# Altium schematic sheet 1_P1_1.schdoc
size 309 x 223 mm; Symbol: Sheet-Symbol_A4; Device: Sheet-Symbol_A4; @Page Name: P1_1; @Page Count: 1; @Page No: 1; @Project Name: 8266; @Schematic Name: Schematic1; @Update Date: 2023-04-14; Company: 嘉立创EDA; Page Size: 4K; Version: V1.0
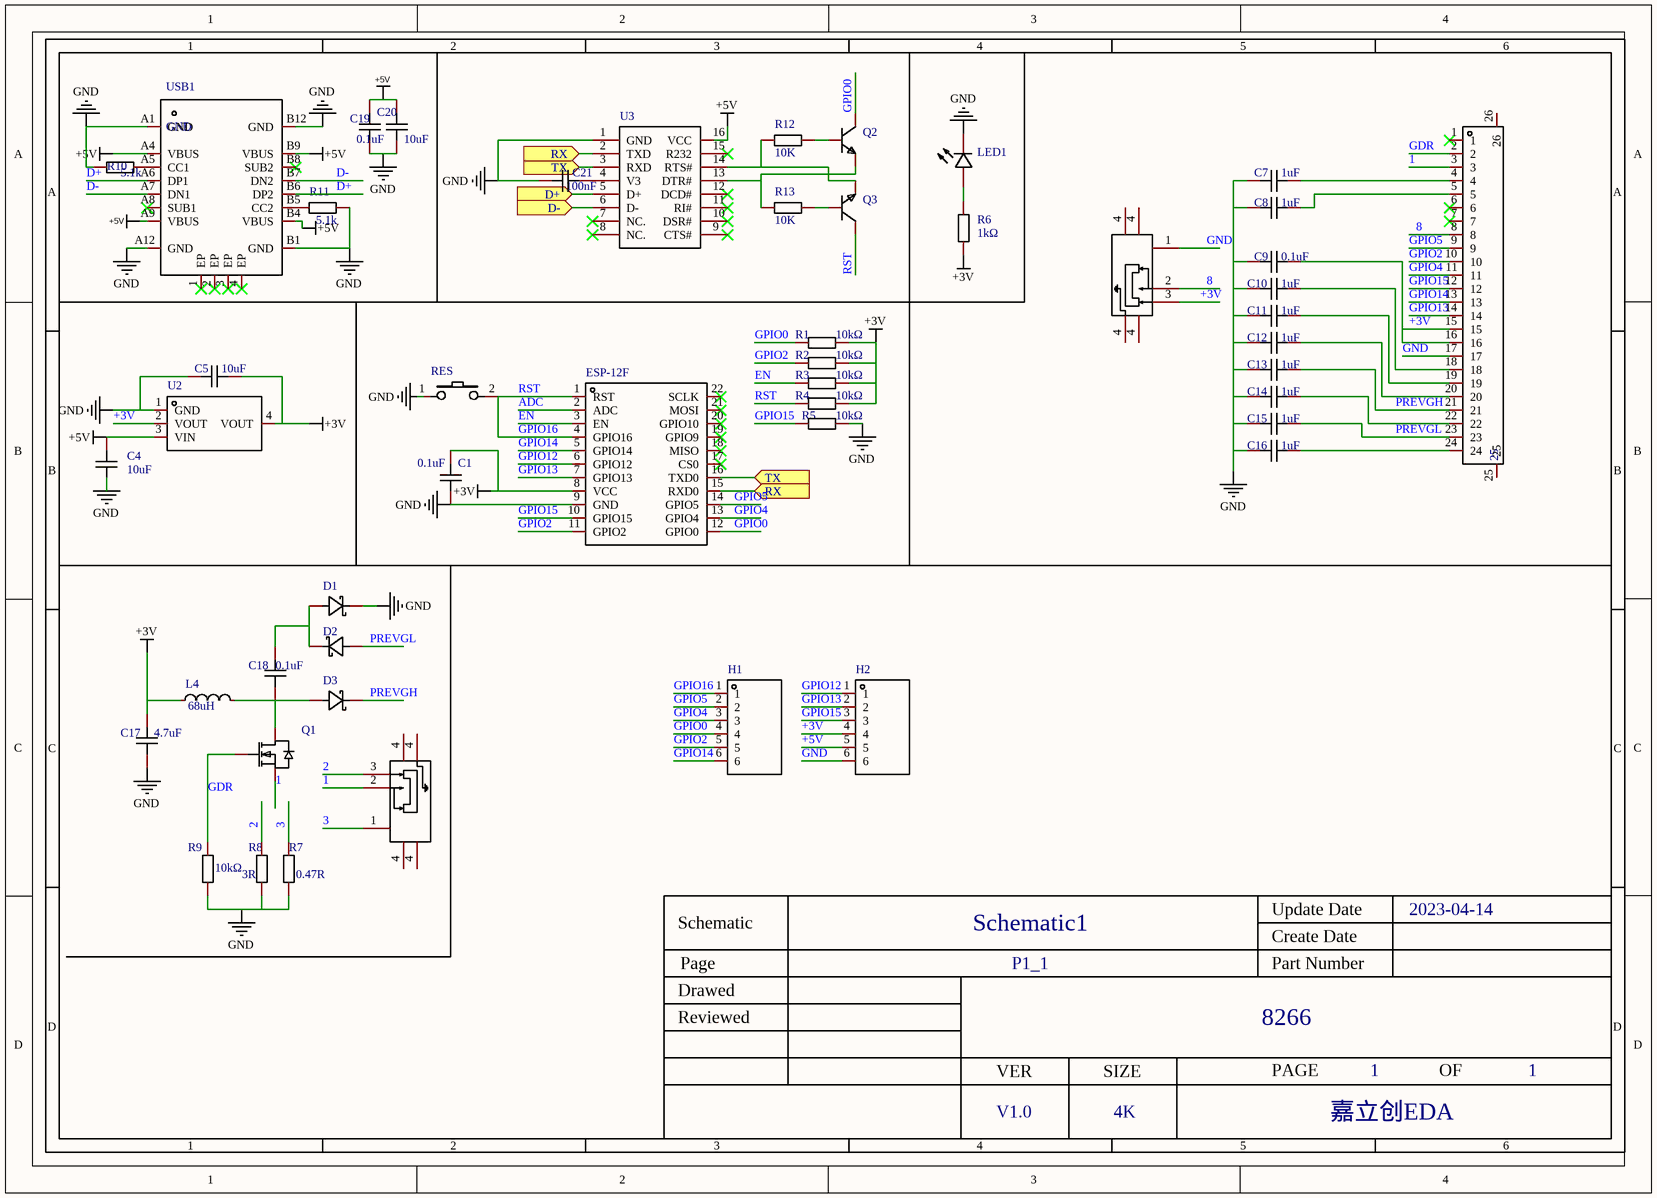
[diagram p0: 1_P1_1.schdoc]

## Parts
C1  value 0.1uF  [C0402]  (hidden comment: CC0603KRX7R9BB104)
C4  value 10uF  [C0402]  (hidden comment: CC0603KRX7R9BB104)
C5  value 10uF  [C0402]  (hidden comment: CC0603KRX7R9BB104)
C7  value 1uF  [C0402]  (hidden comment: CC0603KRX7R9BB104)
C8  value 1uF  [C0402]  (hidden comment: CC0603KRX7R9BB104)
C9  value 0.1uF  [C0402]  (hidden comment: CC0603KRX7R9BB104)
C10  value 1uF  [C0402]  (hidden comment: CC0603KRX7R9BB104)
C11  value 1uF  [C0402]  (hidden comment: CC0603KRX7R9BB104)
C12  value 1uF  [C0402]  (hidden comment: CC0603KRX7R9BB104)
C13  value 1uF  [C0402]  (hidden comment: CC0603KRX7R9BB104)
C14  value 1uF  [C0402]  (hidden comment: CC0603KRX7R9BB104)
C15  value 1uF  [C0402]  (hidden comment: CC0603KRX7R9BB104)
C16  value 1uF  [C0402]  (hidden comment: CC0603KRX7R9BB104)
C17  value 4.7uF  [C0402]  (hidden comment: CC0603KRX7R9BB104)
C18  value 0.1uF  [C0402]  (hidden comment: CC0603KRX7R9BB104)
C19  value 0.1uF  [C0402]  (hidden comment: CC0603KRX7R9BB104)
C20  value 10uF  [C0402]  (hidden comment: CC0603KRX7R9BB104)
C21  value 100nF  [C0603]  (hidden comment: CAP_0603)
D1  MBR0530_C699108  [SOD-123_L2.7-W1.6-LS3.7-RD-1]  (value not drawn)
D2  MBR0530_C699108  [SOD-123_L2.7-W1.6-LS3.7-RD-1]  (value not drawn)
D3  MBR0530_C699108  [SOD-123_L2.7-W1.6-LS3.7-RD-1]  (value not drawn)
ESP-12F  ESP-12F(ESP8266MOD)  [WIFIM-SMD_ESP-12F-ESP8266MOD]  (value not drawn)
FPC1  NAME: 25  [FPC-SMD_24P-P0.50_HDGC_0.5K-BS-24PWB]  (hidden comment: 0.5K-BS-24PWB)
H1  Z-211-0611-0021-001  [HDR-TH_6P-P2.54-V_Z-211-0611-0021-001]  (value not drawn)
H2  Z-211-0611-0021-001  [HDR-TH_6P-P2.54-V_Z-211-0611-0021-001]  (value not drawn)
L4  value 68uH  [IND-SMD_L4.0-W4.0_SWPA4018S]  (hidden comment: SWPA4018S680MT)
LED1  19-217/R6C-AL1M2VY/3T  [LED0603-R-RD]  (value not drawn)
Q1  AO3400  [SOT-23-3_L3.0-W1.7-P0.95-LS2.9-BR]  (value not drawn)
Q2  S8050_NPN  [SOT-23_L2.9-W1.3-P1.90-LS2.4-BR]  (value not drawn)
Q3  S8050_NPN  [SOT-23_L2.9-W1.3-P1.90-LS2.4-BR]  (value not drawn)
R1  value 10kΩ  [R0603]  (hidden comment: TR0603B10K0P0525Z)
R2  value 10kΩ  [R0603]  (hidden comment: TR0603B10K0P0525Z)
R3  value 10kΩ  [R0603]  (hidden comment: TR0603B10K0P0525Z)
R4  value 10kΩ  [R0603]  (hidden comment: TR0603B10K0P0525Z)
R5  value 10kΩ  [R0603]  (hidden comment: TR0603B10K0P0525Z)
R6  value 1kΩ  [R0603]  (hidden comment: TR0603B10K0P0525Z)
R7  value 0.47R  [R0603]  (hidden comment: TR0603B10K0P0525Z)
R8  value 3R  [R0603]  (hidden comment: TR0603B10K0P0525Z)
R9  value 10kΩ  [R0603]  (hidden comment: TR0603B10K0P0525Z)
R10  value 5.1k  [R0603]  (hidden comment: Res_0603)
R11  value 5.1k  [R0603]  (hidden comment: Res_0603)
R12  value 10K  [R0603]  (hidden comment: Res_0603)
R13  value 10K  [R0603]  (hidden comment: Res_0603)
RES  TC-3602-4.3-260G  [KEY-SMD_L6.0-W3.6-LS8.3-L]  (value not drawn)
SW1  MSK12C02  [SW-TH_MSK12C02]  (value not drawn)
SW2  MSK12C02  [SW-TH_MSK12C02]  (value not drawn)
U2  AMS1117-2.5_C498436  [SOT-223-3_L6.7-W3.7-P2.30-LS7.0-BR]  (value not drawn)
U3  CH340C  [SOP-16_L10.0-W3.9-P1.27-LS6.0-BL]  (value not drawn)
USB1  NAME: GND  [USB-C-SMD_KH-TYPE-C-16P]  (hidden comment: USB_TYPE-C-16P)

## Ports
D+ (in), D- (in), RX (in), TX (in)

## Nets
+3V: C1.2 C5.1 C9.2 C17.2 ESP-12F.8(VCC) FPC1.15 FPC1.16 H2.4 L4.1 R1.2 R2.2 R3.2 R4.2 R6.1 SW1.3 U2.2(VOUT) U2.4(VOUT)
+5V: C4.2 C19.2 C20.2 H2.5 U2.3(VIN) U3.16(VCC) USB1.A4(VBUS) USB1.A9(VBUS) USB1.B4(VBUS) USB1.B9(VBUS)
GND: C1.1 C4.1 C5.2 C7.1 C8.1 C9.1 C10.1 C11.1 C12.1 C13.1 C14.1 C15.1 C16.1 C17.1 C19.1 C20.1 C21.1 D1.1(K) ESP-12F.9(GND) FPC1.17 H2.6 LED1.2(C) R5.2 R7.1 R8.1 R9.1 R10.1 R11.2 RES.1 SW1.1 U2.1(GND) U3.1(GND) USB1.A1(GND) USB1.A12(GND) USB1.B1(GND) USB1.B12(GND)
1: FPC1.3 Q1.2(S) SW2.2
2: R8.2 SW2.3
3: R7.2 SW2.1
8: FPC1.8 SW1.2
ADC: ESP-12F.2(ADC)
D+: USB1.A6(DP1) USB1.B6(DP2)
D+: U3.5(D+) ; port D+  [a separate net that carries the same name]
D-: USB1.A7(DN1) USB1.B7(DN2)
D-: U3.6(D-) ; port D-  [a separate net that carries the same name]
EN: ESP-12F.3(EN) R3.1
GDR: FPC1.2 Q1.1(G) R9.2
GPIO0: ESP-12F.12(GPIO0) H1.4 Q2.3(C) R1.1
GPIO2: ESP-12F.11(GPIO2) FPC1.10 H1.5 R2.1
GPIO4: ESP-12F.13(GPIO4) FPC1.11 H1.3
GPIO5: ESP-12F.14(GPIO5) FPC1.9 H1.2
GPIO12: ESP-12F.6(GPIO12) H2.1
GPIO13: ESP-12F.7(GPIO13) FPC1.14 H2.2
GPIO14: ESP-12F.5(GPIO14) FPC1.13 H1.6
GPIO15: ESP-12F.10(GPIO15) FPC1.12 H2.3 R5.1
GPIO16: ESP-12F.1(RST) ESP-12F.4(GPIO16) H1.1 Q3.3(C) R4.1 RES.2  [also labelled RST]
PREVGH: C13.2 D3.1(K) FPC1.21
PREVGL: C15.2 D2.2(A) FPC1.23
RX: ESP-12F.15(RXD0) U3.2(TXD) ; port RX
TX: ESP-12F.16(TXD0) U3.3(RXD) ; port TX
NetC7_2: C7.2 FPC1.4
NetC8_2: C8.2 FPC1.5
NetC10_2: C10.2 FPC1.18
NetC11_2: C11.2 FPC1.19
NetC12_2: C12.2 FPC1.20
NetC14_2: C14.2 FPC1.22
NetC16_2: C16.2 FPC1.24
NetC18_1: C18.1 D3.2(A) L4.2 Q1.3(D)
NetC18_2: C18.2 D1.2(A) D2.1(K)
NetC21_2: C21.2 U3.4(V3)
NetLED1_1: LED1.1(A) R6.2
NetQ2_1: Q2.1(E) R12.2
NetQ2_2: Q2.2(B) R13.1 U3.13(DTR#)
NetQ3_1: Q3.1(E) R13.2
NetQ3_2: Q3.2(B) R12.1 U3.14(RTS#)
NetR10_2: R10.2 USB1.A5(CC1)
NetR11_1: R11.1 USB1.B5(CC2)

Not connected (* = marked no-connect by the designer): ESP-12F 17(CS0)* 18(MISO)* 19(GPIO9)* 20(GPIO10)* 21(MOSI)* 22(SCLK)*; FPC1 1* 6* 7* 25 26; SW1 4; SW2 4; U3 7(NC.)* 8(NC.)* 9(CTS#)* 10(DSR#)* 11(RI#)* 12(DCD#)* 15(R232)*; USB1 1(EP)* 2(EP)* 3(EP)* 4(EP)* A8(SUB1)* B8(SUB2)*

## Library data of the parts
C1 C4 C5 C7-C20 = CC0603KRX7R9BB104: 容值:100nF;精度:±10%;额定电压:50V;材质(温度系数):X7R;; Manufacturer: YAGEO(国巨); Add into BOM: yes; Tolerance: ±10%; Voltage Rated: 50V; Temperature Coefficient: X7R
C21 = CAP_0603: Symbol: C1210X7R475K630NT; Convert to PCB: yes
D1-D3 = MBR0530_C699108: 直流反向耐压(Vr):30V;平均整流电流(Io):500mA;正向压降(Vf):550mV@500mA;; Manufacturer: YANGJIE(扬杰); Add into BOM: yes; Reverse Voltage (Vr): 30V; Average Rectified Current (Io): 500mA
ESP-12F = ESP-12F(ESP8266MOD): 屏蔽罩上的丝印是：ESP8266MOD，ESP8266EX串口WIFI; Manufacturer: Ai-Thinker(安信可); Add into BOM: yes
FPC1 = 0.5K-BS-24PWB: 间距:0.5mm;触点数量:24;锁定特性:抽屉式;安装类型:卧贴;触点类型:上接;工作温度范围:-20~+85;; Manufacturer: HDGC(华德共创); Add into BOM: yes; Pitch: 0.5mm; Number of Contacts: 24; Locking Feature: 抽屉式; FFC, FCB Thickness: 0.3mm
H1 H2 = Z-211-0611-0021-001: 间距:2.54mm;总PIN位数:6;排数:1;插针结构:1x6P;行距:-;安装类型:直插;圆针/方针:方针;额定电流:-;额定电压:-;配合针长度:6mm;塑高:2.5mm;端接针长度:3mm;触头材质:黄铜;触头镀层:-;工作温度范围:-25~+105;颜色:黑色;; Manufacturer: Nextron(正凌); Add into BOM: yes; Pitch: 2.54mm; Pin Structure: 1x6P; Circluar Pins/Square Pins: 方针
L4 = SWPA4018S680MT: 直流电阻(DCR):1.3Ω;精度:±20%;电感值:68uH;额定电流:320mA;; Manufacturer: Sunlord(顺络); Add into BOM: yes; DC Resistance (DCR): 1.3Ω; Tolerance: ±20%; Rated Current: 320mA
LED1 = 19-217/R6C-AL1M2VY/3T: 发光颜色:红灯;二极管配置:-;透镜颜色:无色透明;主波长:617.5nm;峰值波长:632nm;色温:-;光通量(25时):-;测试电流:5mA;正向电压(VF):2.2V;发光强度:28.5mcd;功率:60mW;发光角度:120°;安装方式:-;工作温度:-40~+85;; Manufacturer: EVERLIGHT(台湾亿光); Add into BOM: yes; Emitted Color: 红灯; Lens Color: 无色透明; Peak Wavelength: 632nm; Forward Current: 5mA; Forward Voltage (VF): 2.2V; Power Dissipation: 60mW; Viewing Angle: 120°
Q1 = AO3400: 类型:N管;漏源电压(Vdss):30V;连续漏极电流(Id):5.8A;功率(Pd):1.4W;导通电阻(RDS(on)@Vgs,Id):29mΩ@10V,5.8A;阈值电压(Vgs(th)@Id):1.1V@250A;栅极电荷(Qg@Vgs):9.7nC@4.5V;输入电容(Ciss@Vds):823pF@15V;反向传输电容(Crss@Vds):77pF@15V;工作温度:-50~+150;; Manufacturer: YFW(佑风微); Symbol: AO3400_C2977509; Add into BOM: yes; Type: N管; Drain Source Voltage (Vdss): 30V; Power Dissipation (Pd): 1.4W
Q2 Q3 = S8050_NPN: 晶体管类型:NPN;集射极击穿电压(Vceo):25V;集电极电流(Ic):500mA;功率(Pd):300mW;集电极-发射极饱和电压(VCE(sat)@Ic,Ib):600mV@500mA,50mA;直流电流增益(hFE@Ic,Vce):-;特征频率(fT):150MHz;工作温度:+150@(Tj);; Symbol: NPN; Convert to PCB: yes
R1-R9 = TR0603B10K0P0525Z: 阻值:10kΩ;精度:±0.1%;温度系数:±25ppm/;功率:100mW;工作温度范围:-55~+155;电阻类型:薄膜电阻;最大工作电压:75V;; Manufacturer: EVER OHMS(天二科技); Symbol: TR0603B10KP05250.1W; Add into BOM: yes; Tolerance: ±0.1%; Temperature Coefficient: ±25ppm/; Power(Watts): 100mW; Overload Voltage (Max): 75V
R10-R13 = Res_0603: Symbol: 电阻; Convert to PCB: yes
RES = TC-3602-4.3-260G: Manufacturer: HCTL(华灿天禄); Symbol: TC-3602-4.3-260GKK; Add into BOM: yes
SW1 SW2 = MSK12C02: Manufacturer: SHOU HAN(首韩); Add into BOM: yes
U2 = AMS1117-2.5_C498436: 输出类型:-;; Manufacturer: Slkor(萨科微); Add into BOM: yes
U3 = CH340C: 类型:Transceiver;协议类别:USB 2.0;驱动器/接收器数:-;数据速率:2Mbps;; Manufacturer: WCH(南京沁恒); Add into BOM: yes; Protocol: USB 2.0; Data Rate: 2Mbps; Supply Voltage: 3.3V, 5V
USB1 = USB_TYPE-C-16P: 连接器类型:Type-C;标准:-;公母:母座;触点数量:16;端口数量:1;安装方式:卧贴;额定电流 - 电源:3A;工作温度范围:-40~+85;; Symbol: KH-TYPE-C-16P; Add into BOM: yes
